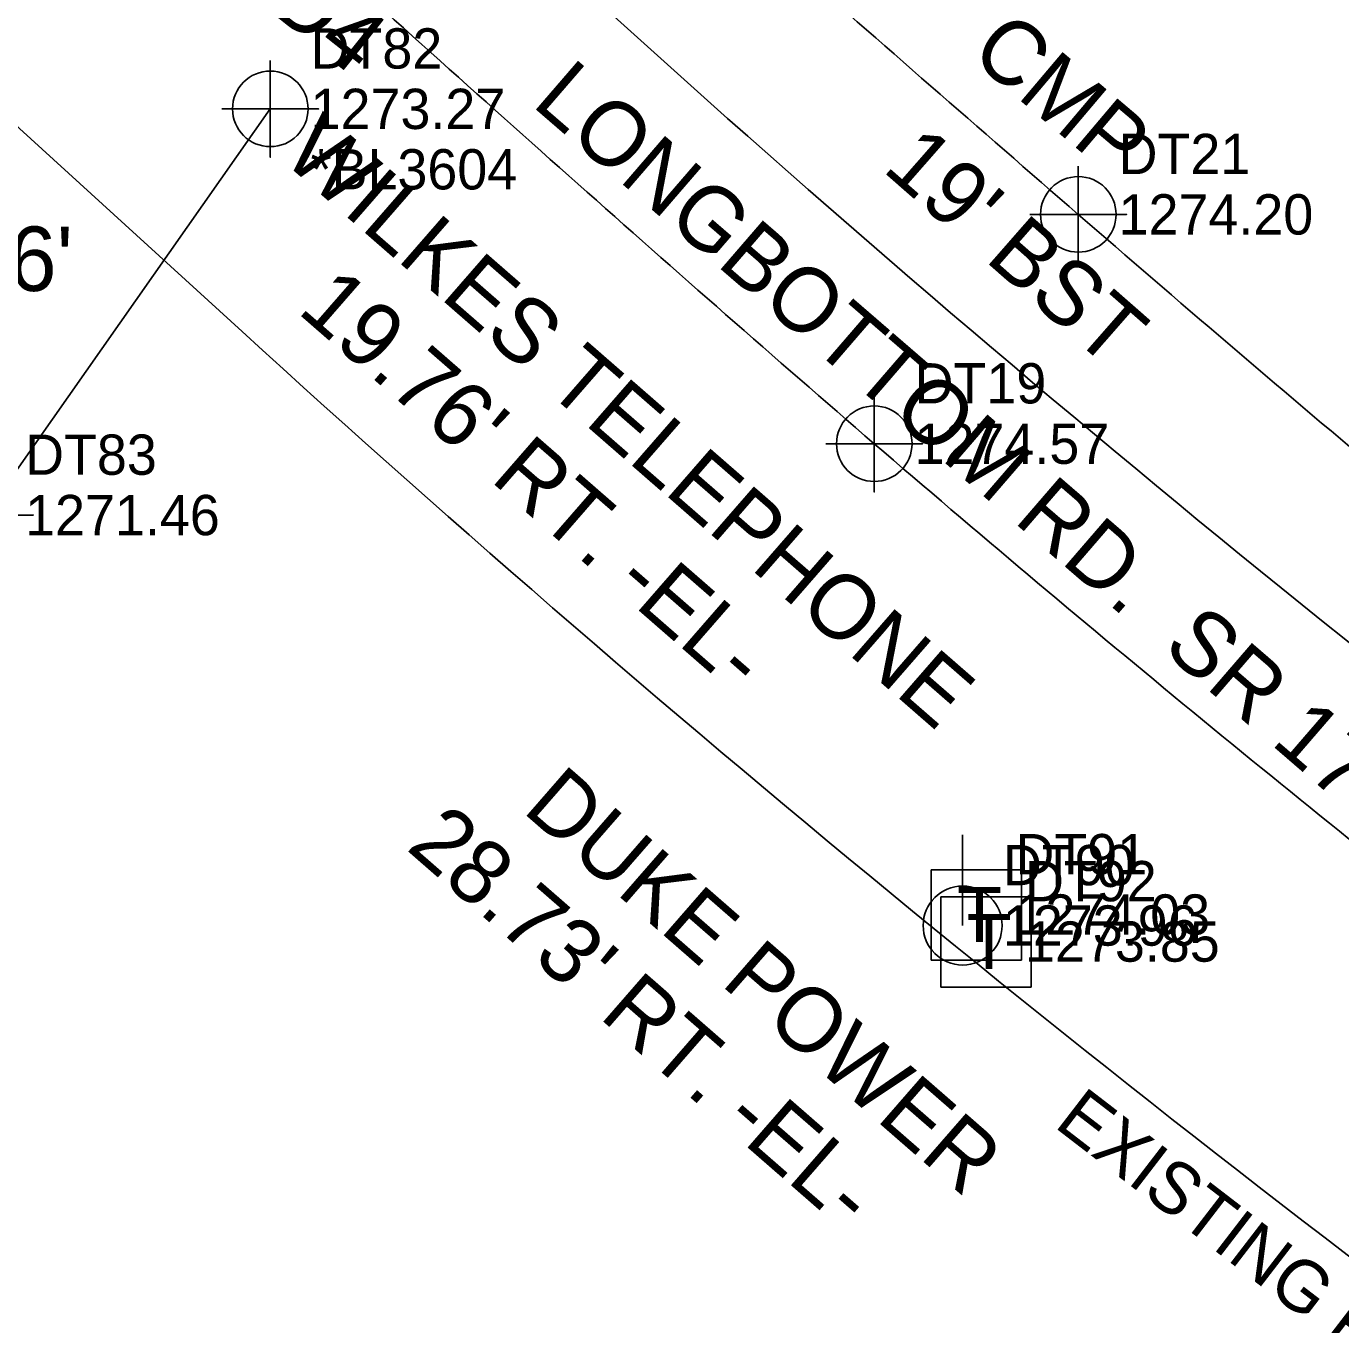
# Model space of a CAD drawing. Extents: x 1390773 to 1392296, y 959928 to 960736.
# Drawn here: x 1391644.1 to 1391725.7, y 960204.3 to 960284.9 of the extents above; entities that cross this region are included whole.
import ezdxf

# ---------------------------------------------------------------- set-up
doc = ezdxf.new("R2010")
doc.units = 0
for name, color, linetype in [('Exist Horizontal Alignment', 7, 'Continuous'), ('Exist Other Culture Located Object Text', 7, 'Continuous'), ('Exist Right of Way Line', 7, 'Continuous'), ('Exist Right of Way Line Text', 7, 'Continuous'), ('Exist Roads EOP', 7, 'Continuous'), ('Exist Roads EOP Cogo Elevation', 7, 'Continuous'), ('Exist Roads EOP Cogo Number', 7, 'Continuous'), ('Exist Roads EOP Cogo Point CELL', 7, 'Continuous'), ('Exist Roads EOP Text', 7, 'Continuous'), ('Exist Structure Major Bridge Seat Top Elevation', 7, 'Continuous'), ('Exist Structure Minor Pipes CMP 15 Inch Text', 7, 'Continuous'), ('Exist Utilities Power Pole CELL', 7, 'Continuous'), ('Exist Utilities Power Pole Cogo Elevation', 7, 'Continuous'), ('Exist Utilities Power Pole Cogo Number', 7, 'Continuous'), ('Exist Utilities Telephone Pedestal CELL', 7, 'Continuous'), ('Exist Utilities Telephone Pedestal Cogo Elevation', 7, 'Continuous'), ('Exist Utilities Telephone Pedestal Cogo Number', 7, 'Continuous'), ('Exist Utilities Telephone Pole Text', 7, 'Continuous'), ('Exist Vegetation Woods Line', 7, 'Continuous'), ('Exist Vegetation Woods Line Cogo Comment', 7, 'Continuous'), ('Exist Vegetation Woods Line Cogo Elevation', 7, 'Continuous'), ('Exist Vegetation Woods Line Cogo Number', 7, 'Continuous'), ('Exist Vegetation Woods Line Cogo Point CELL', 7, 'Continuous')]:
    doc.layers.add(name, color=color, linetype=linetype)

msp = doc.modelspace()

# ---------------------------------------------------------------- linework, layer by layer
at = {"layer": 'Exist Horizontal Alignment'}
msp.add_arc((1392351.427, 961027.032), 1000, 227.643038, 233.763828, dxfattribs=at)
at = {"layer": 'Exist Right of Way Line'}
msp.add_line((1391525.055, 960386.628), (1391657.467, 960265.902), dxfattribs=at)
for radius in [970, 1030]:
    msp.add_arc((1392351.427, 961027.032), radius, 227.643038, 233.763828, dxfattribs=at)
at = {"layer": 'Exist Roads EOP'}
for points in [[(1391915.673, 960148.156), (1391871.111, 960166.209), (1391827.705, 960187.765), (1391786.031, 960213.485), (1391746.988, 960241.829), (1391709.378, 960273.178), (1391672.886, 960305.161)], [(1391909.259, 960130.384), (1391863.262, 960148.577), (1391817.991, 960171.223), (1391775.806, 960197.201), (1391735.389, 960227.09), (1391696.713, 960258.946), (1391660.088, 960291.389)]]:
    msp.add_spline(points, degree=3, dxfattribs=at)
at = {"layer": 'Exist Roads EOP Cogo Point CELL'}
for points in [[(1391709.378, 960276.178), (1391709.378, 960270.178), (1391709.378, 960273.178), (1391712.378, 960273.178), (1391706.378, 960273.178)], [(1391696.713, 960261.946), (1391696.713, 960255.946), (1391696.713, 960258.946), (1391699.713, 960258.946), (1391693.713, 960258.946)]]:
    msp.add_lwpolyline(points, dxfattribs=at)
for centre in [(1391709.378, 960273.178), (1391696.713, 960258.946)]:
    msp.add_circle(centre, 2.344, dxfattribs=at)
at = {"layer": 'Exist Utilities Power Pole CELL'}
for q in [(1391702.198, 960234.67), (1391702.198, 960229.045)]:
    msp.add_line((1391702.198, 960229.045), q, dxfattribs=at)
msp.add_circle((1391702.198, 960229.045), 2.45, dxfattribs=at)
at = {"layer": 'Exist Utilities Telephone Pedestal CELL'}
for p, q in [((1391702.976, 960229.727), (1391702.976, 960229.727)), ((1391703.571, 960228.05), (1391703.571, 960228.05))]:
    msp.add_line(p, q, dxfattribs=at)
for points in [[(1391700.252, 960226.901), (1391705.846, 960226.901), (1391705.846, 960232.496), (1391700.252, 960232.496), (1391700.252, 960226.901)], [(1391700.847, 960225.224), (1391706.441, 960225.224), (1391706.441, 960230.819), (1391700.847, 960230.819), (1391700.847, 960225.224)]]:
    msp.add_lwpolyline(points, dxfattribs=at)
at = {"layer": 'Exist Vegetation Woods Line'}
msp.add_lwpolyline([(1391659.219, 960279.726), (1391641.498, 960254.518), (1391628.66, 960218.377)], dxfattribs=at)
at = {"layer": 'Exist Vegetation Woods Line Cogo Point CELL'}
for points in [[(1391659.219, 960282.726), (1391659.219, 960276.726), (1391659.219, 960279.726), (1391662.219, 960279.726), (1391656.219, 960279.726)], [(1391641.498, 960257.518), (1391641.498, 960251.518), (1391641.498, 960254.518), (1391644.498, 960254.518), (1391638.498, 960254.518)]]:
    msp.add_lwpolyline(points, dxfattribs=at)
msp.add_circle((1391659.219, 960279.726), 2.344, dxfattribs=at)

# ---------------------------------------------------------------- texts
at = {"layer": 'Exist Other Culture Located Object Text'}
msp.add_text('BD4', height=4, rotation=321.50919, dxfattribs=at).set_placement((1391656.158, 960288.187))
at = {"layer": 'Exist Right of Way Line Text'}
msp.add_text('EXISTING R/W', height=3.2, rotation=322.42504, dxfattribs=at).set_placement((1391707.806, 960216.59))
at = {"layer": 'Exist Roads EOP Cogo Elevation'}
for s, p in [('1274.20', (1391711.878, 960271.928)), ('1274.57', (1391699.213, 960257.696))]:
    msp.add_text(s, height=2.5, dxfattribs=at).set_placement(p)
at = {"layer": 'Exist Roads EOP Cogo Number'}
for s, p in [('DT21', (1391711.878, 960275.678)), ('DT19', (1391699.213, 960261.446))]:
    msp.add_text(s, height=2.5, dxfattribs=at).set_placement(p)
at = {"layer": 'Exist Roads EOP Text'}
for s, rotation, p in [('LONGBOTTOM RD.  SR 1737', 319.18376, (1391675.374, 960279.97)), ("19' BST", 318.76742, (1391697.139, 960275.927))]:
    msp.add_text(s, height=4, rotation=rotation, dxfattribs=at).set_placement(p)
at = {"layer": 'Exist Structure Major Bridge Seat Top Elevation'}
msp.add_text("SEAT=1271.26'", height=4, dxfattribs=at).set_placement((1391609.523, 960268.426))
at = {"layer": 'Exist Structure Minor Pipes CMP 15 Inch Text'}
msp.add_text('15" CMP', height=4, rotation=319.75846, dxfattribs=at).set_placement((1391695.408, 960289.007))
at = {"layer": 'Exist Utilities Power Pole Cogo Elevation'}
msp.add_text('1273.96', height=2.5, dxfattribs=at).set_placement((1391704.698, 960227.795))
at = {"layer": 'Exist Utilities Power Pole Cogo Number'}
msp.add_text('DT90', height=2.5, dxfattribs=at).set_placement((1391704.698, 960231.545))
at = {"layer": 'Exist Utilities Telephone Pedestal CELL'}
for p in [(1391701.845, 960228.014), (1391702.44, 960226.337)]:
    msp.add_text('T', height=3.42, dxfattribs=at).set_placement(p)
at = {"layer": 'Exist Utilities Telephone Pedestal Cogo Elevation'}
for s, p in [('1274.03', (1391705.476, 960228.477)), ('1273.85', (1391706.071, 960226.8))]:
    msp.add_text(s, height=2.5, dxfattribs=at).set_placement(p)
at = {"layer": 'Exist Utilities Telephone Pedestal Cogo Number'}
for s, p in [('DT91', (1391705.476, 960232.227)), ('DT92', (1391706.071, 960230.55))]:
    msp.add_text(s, height=2.5, dxfattribs=at).set_placement(p)
at = {"layer": 'Exist Utilities Telephone Pole Text'}
for s, p in [('WILKES TELEPHONE', (1391659.836, 960276.613)), ("19.76' RT. -EL-", (1391660.824, 960267.129)), ('DUKE POWER', (1391674.794, 960236.143)), ("28.73' RT. -EL-", (1391667.579, 960233.809))]:
    msp.add_text(s, height=4, rotation=318.9216, dxfattribs=at).set_placement(p)
at = {"layer": 'Exist Vegetation Woods Line Cogo Comment'}
msp.add_text('*BL3604', height=2.5, dxfattribs=at).set_placement((1391661.719, 960274.726))
at = {"layer": 'Exist Vegetation Woods Line Cogo Elevation'}
for s, p in [('1273.27', (1391661.719, 960278.476)), ('1271.46', (1391643.998, 960253.268))]:
    msp.add_text(s, height=2.5, dxfattribs=at).set_placement(p)
at = {"layer": 'Exist Vegetation Woods Line Cogo Number'}
for s, p in [('DT82', (1391661.719, 960282.226)), ('DT83', (1391643.998, 960257.018))]:
    msp.add_text(s, height=2.5, dxfattribs=at).set_placement(p)

doc.saveas('drawing.dxf')
